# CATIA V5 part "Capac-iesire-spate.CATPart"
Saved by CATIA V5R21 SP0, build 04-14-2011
Part number: Part1
Bounding box of the stored display mesh (mm): x -54.814 to 54.83, y 0 to 21.5, z -55 to 54.2
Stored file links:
  C:\Users\MIRCEA\Desktop\MOM\Mogan\model\Capac-iesire-spate.CATPart
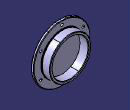
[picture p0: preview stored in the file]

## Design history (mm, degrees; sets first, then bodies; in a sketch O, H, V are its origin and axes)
Body1 (main body)
  Sketch1 on yz-plane, origin (0, 0, 0), H (0, 1, 0), V (0, 0, 1)
    line L1 (0, 0) -> (5, 0)
    line L2 (0, 0) -> (0, 55)
    line L3 (0, 55) -> (5, 55)
    line L4 (5, 55) -> (5, 40)
    line L5 (5, 40) -> (21.5, 40)
    line L6 (21.5, 40) -> (21.5, 35)
    line L7 (21.5, 35) -> (5, 35)
    point P7 (5, 35)
    line L8 (5, 35) -> (5, 0)
    length L1 = 5
    length L2 = 55
    length L4 = 15
    length L5 = 16.5
    length L6 = 5
    horizontal: L1 H, L3 H, L5 H, L7 H
    vertical: L2 V, L4 V, L6 V, L8 V
    coincidence: P7 L4
  Shaft1: profile Sketch1, axis Sketch1.L1, angle 360
  Sketch2 on face of Shaft1 from Sketch1.L2, origin (0, 0, 0), H (1, 0, 0), V (0, 0, 1)
    point P1 (0, 47.5)
  Sketch3 on face of Shaft1 from Sketch1.L2, origin (0, 0, 47.5), H (1, 0, 0), V (0, 0, 1)
    point P1 (0, 0)
    reference projected point E1 (0, 0) from Sketch2.P1
    coincidence: E1 P1
  Hole1: placed by Sketch3, at (0, 0, 47.5) direction (0, 1, 0), diameter 5, through (limit type 6)
  CircPattern1: of Hole1, instances 6, angular step 60 {= 360.0*1 deg/CircPattern1.AngularNumber}, axis from face of Shaft1 from Sketch1.L2
  Sketch4 on zx-plane, origin (0, 0, 0), H (-1, 0, 0), V (0, 0, 1)
    line L1 (0, 54.2) -> (14.9451, 54.2)
    line L2 (0, 54.2) -> (-11.9737, 54.2)
    line L3 (-11.9737, 54.2) -> (-11.9737, 55.4989)
    line L4 (14.9451, 54.2) -> (14.9451, 55.4989)
    line L5 (14.9451, 55.4989) -> (-11.9737, 55.4989)
    horizontal: L1 H, L2 H, L5 H
    vertical: L3 V, L4 V
  Pocket1: profile Sketch4, direction (0, 1, 0), length 20
  Chamfer1: length 1, angle 45, on edge [face of Shaft1 from Sketch1.L2 | face of Shaft1 from Sketch1.L3]; edge [face of Shaft1 from Sketch1.L3 | face of Shaft1 from Sketch1.L4]; edge [face of Shaft1 from Sketch1.L5 | face of Shaft1 from Sketch1.L6]; edge [face of Shaft1 from Sketch1.L6 | face of Shaft1 from Sketch1.L7]
  Sketch5 on yz-plane, origin (0, 0, 0), H (0, 1, 0), V (0, 0, 1)
    line L1 (5.1254, 41.2475) -> (4.8069, 40.2876)
    arc A1 centre (5.3501, 40.1074) radius 0.5723 from (4.8069, 40.2876) to (5.3152, 39.5361) ccw
    line L2 (5.3152, 39.5361) -> (5.6031, 39.5185)
    arc A2 centre (5.6979, 41.0738) radius 1.5582 from (5.6031, 39.5185) to (6.8045, 39.9768) ccw
    tangency: A1 L1, L2 A1, A2 L2
  Groove1: profile Sketch5, axis axis of face of Shaft1 from Sketch1.L7, angle 360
